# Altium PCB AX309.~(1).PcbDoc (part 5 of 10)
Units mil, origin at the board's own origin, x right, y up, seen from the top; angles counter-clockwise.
Board outline 5185 x 3614 mil, 4 copper layers (Top Layer, GND, Mid-Layer 1, Bottom Layer); 191 components, 352 nets, 1106 pads, 425 vias.
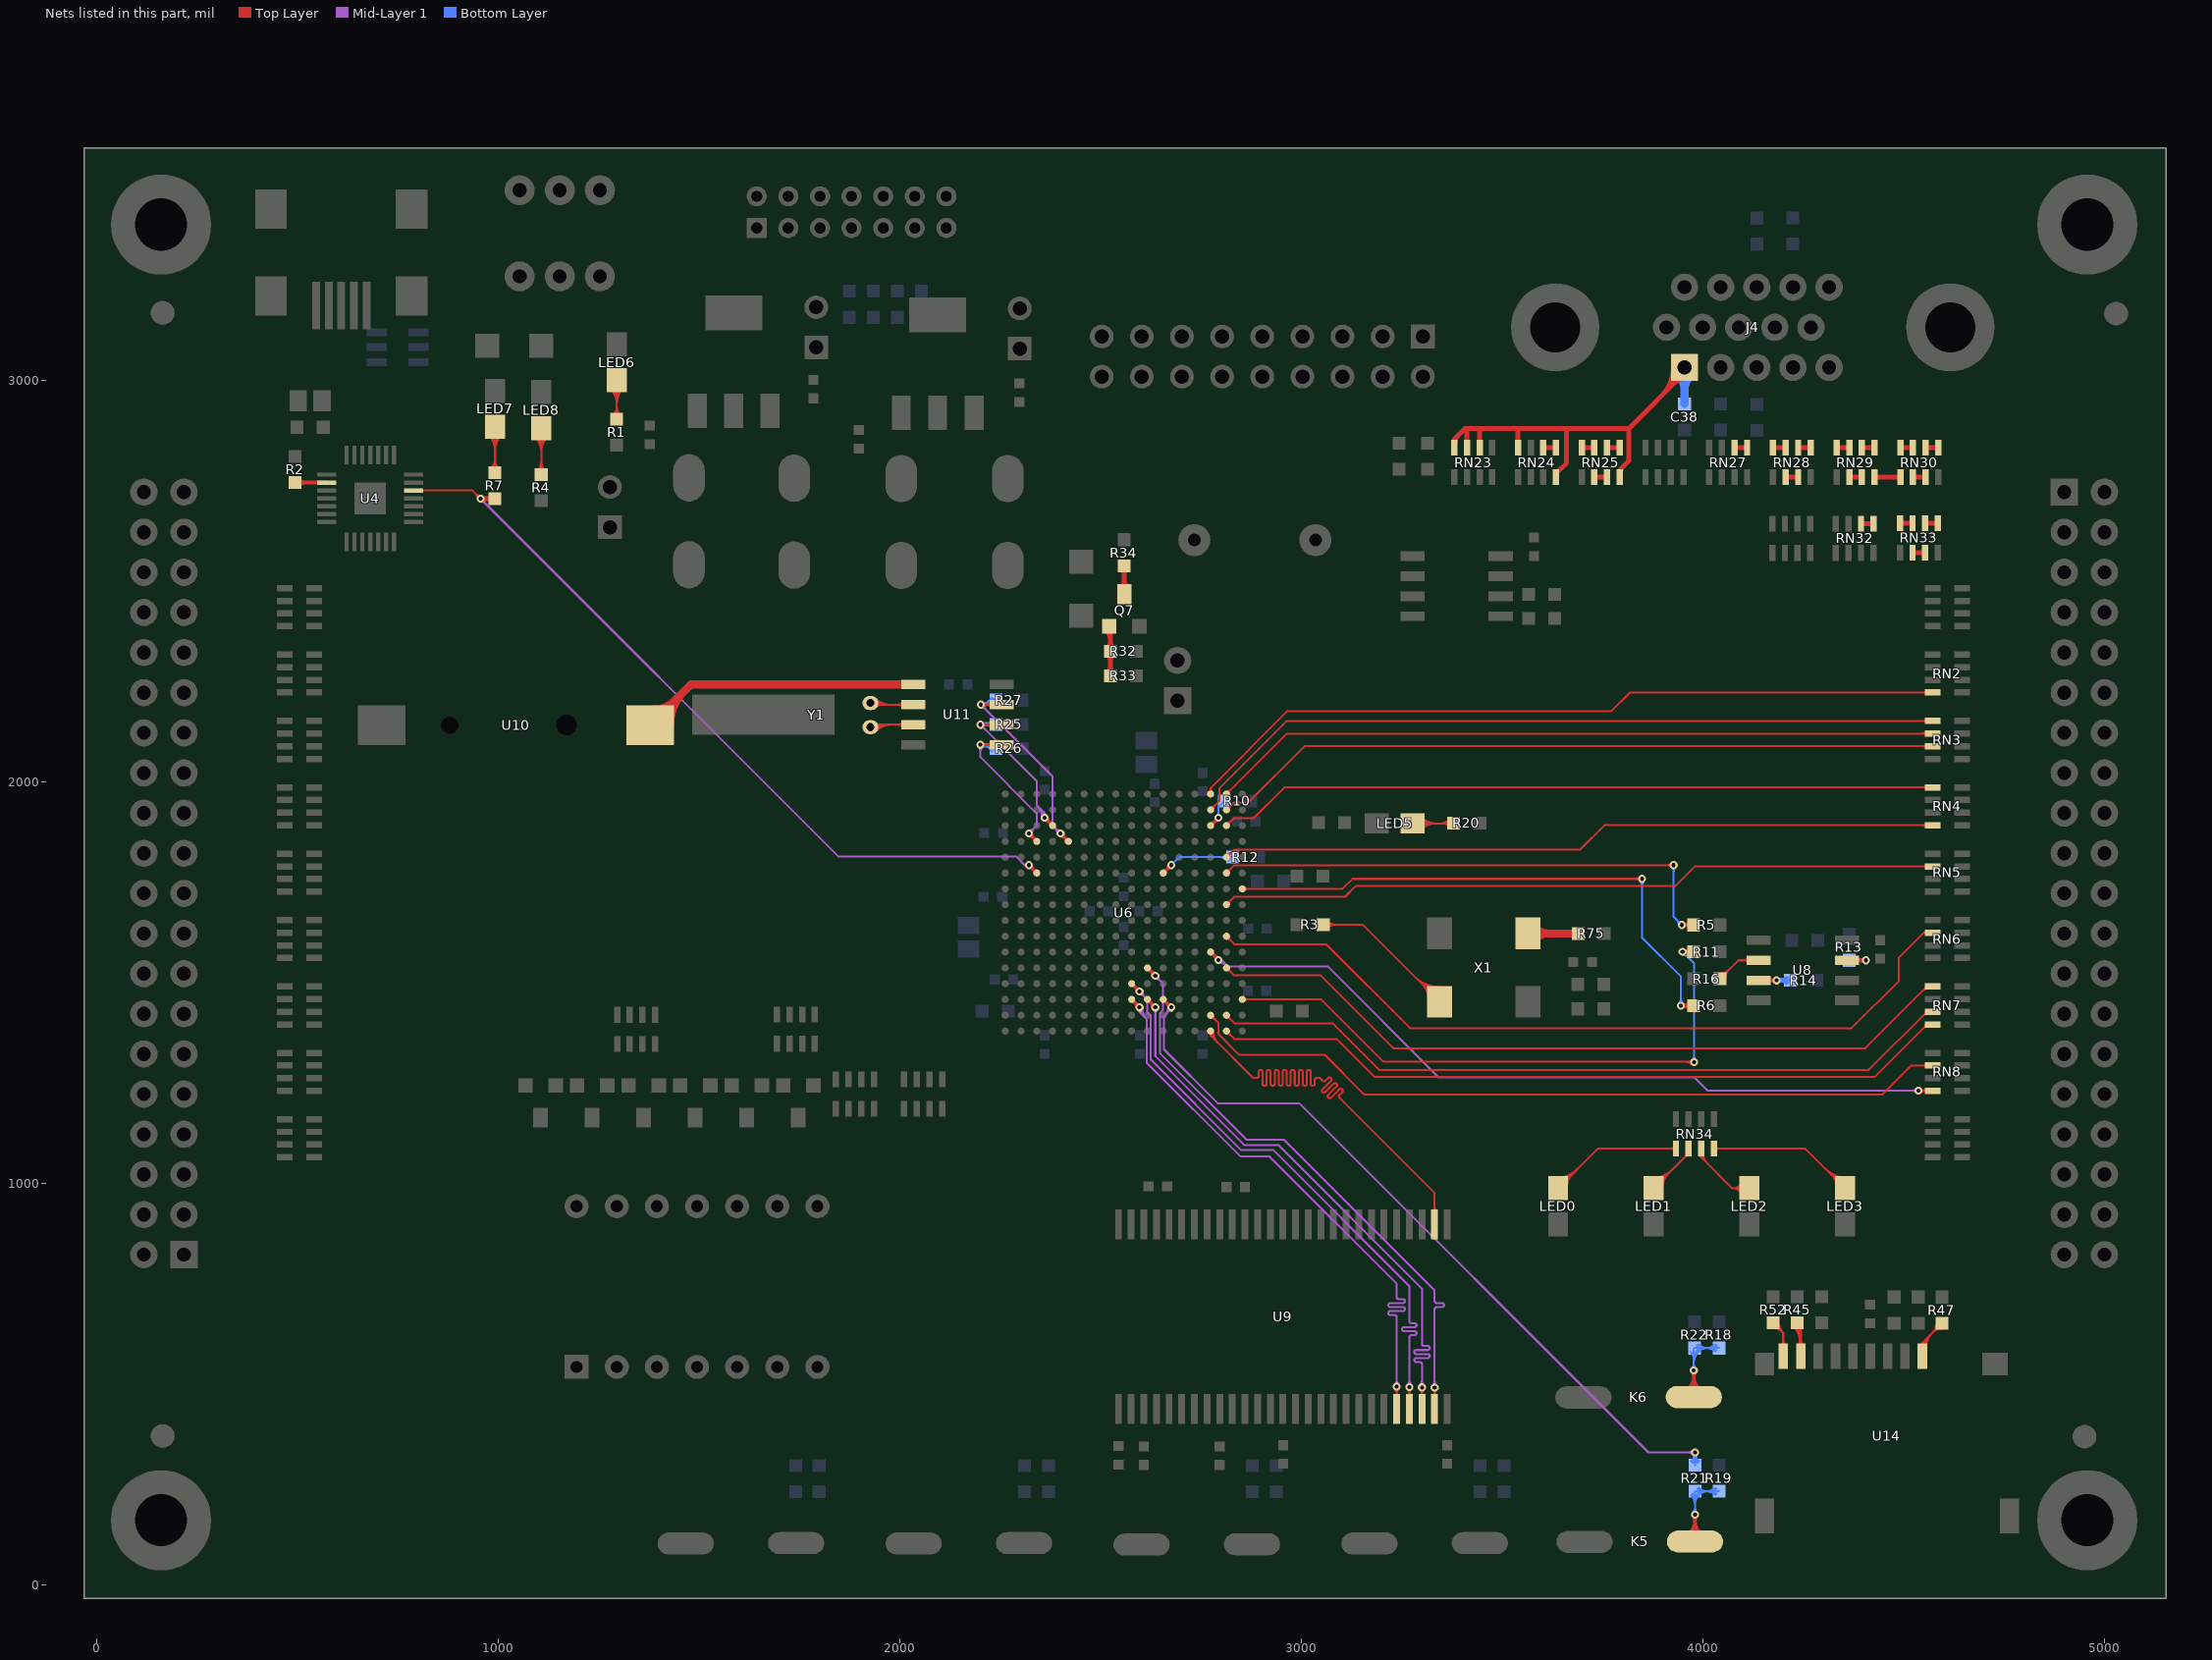
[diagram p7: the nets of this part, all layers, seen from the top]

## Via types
v1: diameter 20, hole 10, Top Layer to Bottom Layer, 328 vias
v2: diameter 30, hole 15, Top Layer to Bottom Layer, 95 vias
v3: diameter 40, hole 20, Top Layer to Bottom Layer, 2 vias

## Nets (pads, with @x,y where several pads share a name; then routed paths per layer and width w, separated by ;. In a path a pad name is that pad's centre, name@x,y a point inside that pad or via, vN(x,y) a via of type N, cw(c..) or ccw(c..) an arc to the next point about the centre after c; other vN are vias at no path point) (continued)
NetK5_1: K5.1 R19.2 R21.2 | length 782.9
  Top Layer w5: K5.1@3963.28,124.72 ccw(c3920.5,167.5) 3981,167.5 ccw(c4041.5,167.5) K5.1@3998.72,124.72 ; K5.1@3966.82,121.18 ccw(c3932.57,155.43) 3981,155.43 ccw(c4029.43,155.43) K5.1@3995.18,121.18 ; K5.1@3970.35,117.65 ccw(c3944.64,143.36) 3981,143.36 ccw(c4017.36,143.36) K5.1@3991.65,117.65 ; v1@3974.95,169.57 cw(c3957.6,156.87) 3978.85,153.58 ; v1@3975.7,168.7 cw(c3962.89,155.89) 3981,155.89 cw(c3999.11,155.89) v1@3986.3,168.7 ; v1@3976.57,167.95 cw(c3967.88,156.08) 3982.42,158.33 ; K5.1@3977,103 K5.1@3981,107 v1(3981,174) ; 3979.58,158.33 cw(c3994.12,156.08) v1@3985.43,167.95 ; 3983.15,153.58 cw(c4004.4,156.87) v1@3987.05,169.57
  Bottom Layer w5: R21.2@3971.45,222.45 cw(c3948.41,199.41) 3981,199.41 cw(c4013.59,199.41) 3990.55,222.45 cw(c4013.59,199.41) 4013.59,232 cw(c4013.59,264.59) R21.2@3990.55,241.55 ; R21.2@3974.99,225.99 cw(c3960.48,211.48) 3981,211.48 cw(c4001.52,211.48) 3987.01,225.99 cw(c4001.52,211.48) 4001.52,232 cw(c4001.52,252.52) R21.2@3987.01,238.01 ; v1@3975.7,179.3 ccw(c3962.89,192.11) 3981,192.11 ccw(c3999.11,192.11) v1@3986.3,179.3 ; v1(3981,174) R21.2@3981,232 R19.2@4041,232 ; R19.2@4031.45,222.45 ccw(c4008.41,199.41) 4008.41,232 ccw(c4008.41,264.59) R19.2@4031.45,241.55 ; R19.2@4034.99,225.99 ccw(c4020.48,211.48) 4020.48,232 ccw(c4020.48,252.52) R19.2@4034.99,238.01
NetK6_2: K6.2 R18.2 R22.2 | length 765.3
  Top Layer w5: K6.2@3960.28,484.72 ccw(c3917.5,527.5) 3978,527.5 ccw(c4038.5,527.5) K6.2@3995.72,484.72 ; K6.2@3963.82,481.18 ccw(c3929.57,515.43) 3978,515.43 ccw(c4026.43,515.43) K6.2@3992.18,481.18 ; K6.2@3967.35,477.65 ccw(c3941.64,503.36) 3978,503.36 ccw(c4014.36,503.36) K6.2@3988.65,477.65 ; v1@3971.91,528.62 cw(c3954.75,516.28) 3975.61,512.87 ; v1@3972.7,527.7 cw(c3959.89,514.89) 3978,514.89 cw(c3996.11,514.89) v1@3983.3,527.7 ; v1@3973.62,526.91 cw(c3964.82,514.67) 3979.7,517.1 ; 3976.3,517.1 cw(c3991.18,514.67) v1@3982.38,526.91 ; K6.2@3978,467 v1(3978,533) ; 3980.39,512.87 cw(c4001.25,516.28) v1@3984.09,528.62
  Bottom Layer w5: R22.2@3970.45,579.45 cw(c3952.24,561.24) 3978,561.24 ; v1@3972.7,538.3 ccw(c3959.89,551.11) 3978,551.11 ccw(c3996.11,551.11) v1@3983.3,538.3 ; v1(3978,533) 3978,587 R22.2@3980,589 R18.2@4041,589 ; 3978,551.58 cw(c4017.42,551.58) 3989.55,579.45 cw(c4012.59,556.41) 4012.59,589 cw(c4012.59,621.59) R22.2@3989.55,598.55 ; 3978,563.65 cw(c4005.35,563.65) 3986.01,582.99 cw(c4000.52,568.48) 4000.52,589 cw(c4000.52,609.52) R22.2@3986.01,595.01 ; R18.2@4031.45,579.45 ccw(c4008.41,556.41) 4008.41,589 ccw(c4008.41,621.59) R18.2@4031.45,598.55 ; R18.2@4034.99,582.99 ccw(c4020.48,568.48) 4020.48,589 ccw(c4020.48,609.52) R18.2@4034.99,595.01
NetLED0_1: LED0.1 RN34.5 | length 578.7
  Top Layer w5: LED0.1@3640,987 3738.85,1085.85 RN34.5@3933.51,1085.85 RN34.5@3933.51,1070.51 ; LED0.1@3640,999.5 ccw(c3640,1029.68) LED0.1@3661.34,1008.34 ; LED0.1@3640,1004.5 ccw(c3640,1046.75) 3669.87,1016.87 ; LED0.1@3640,1009.5 ccw(c3640,1063.82) 3678.41,1025.41 ; LED0.1@3640,1014.5 ccw(c3640,1080.89) 3686.95,1033.95 ; LED0.1@3657.5,992 cw(c3687.68,992) 3666.34,1013.34 ; LED0.1@3662.5,992 cw(c3704.75,992) 3674.87,1021.87 ; RN34.5@3929.71,1082.05 ccw(c3920.54,1072.88) 3920.54,1085.85 ccw(c3920.54,1098.82) RN34.5@3929.71,1089.65
NetLED1_1: LED1.1 RN34.6 | length 363.7
  Top Layer w5: LED1.1@3878.33,987 3965.01,1073.67 RN34.6@3965.01,1085.85 ; LED1.1@3878.33,999.5 ccw(c3878.33,1029.68) LED1.1@3899.67,1008.34 ; LED1.1@3878.33,1004.5 ccw(c3878.33,1046.75) 3908.21,1016.87 ; LED1.1@3878.33,1009.5 ccw(c3878.33,1063.82) 3916.74,1025.41 ; LED1.1@3878.33,1014.5 ccw(c3878.33,1080.89) 3925.28,1033.95 ; LED1.1@3895.83,992 cw(c3926.01,992) 3904.67,1013.34 ; LED1.1@3900.83,992 cw(c3943.08,992) 3913.21,1021.87 ; 3955.58,1064.24 ccw(c3945.78,1074.04) RN34.6@3959.63,1074.04 ; 3956.46,1065.12 cw(c3965.01,1056.57) RN34.6@3965.01,1068.66
NetLED2_1: LED2.1 RN34.7 | length 355.3
  Top Layer w5: RN34.7@3991.88,1074.04 ccw(c4003.75,1074.04) 3995.35,1065.65 ; RN34.7@3993.72,1069.44 cw(c3990.72,1064.5) 3996.5,1064.5 ; RN34.7@3996.5,1085.85 3996.5,1064.5 ; RN34.7@3996.88,1074.04 ccw(c4020.82,1074.04) 4003.89,1057.11 ; RN34.7@3999.29,1069.44 ccw(c4002.29,1064.5) 3996.5,1064.5 ; RN34.7@4001.88,1074.04 ccw(c4037.89,1074.04) 4012.43,1048.57 ; LED2.1@4098.1,974.29 ccw(c4074,957.8) 4074,987 ; LED2.1@4098.1,999.71 cw(c4074,1016.2) 4074,987 ; LED2.1@4102.23,977.12 ccw(c4083.48,964.29) 4083.48,987 ccw(c4083.48,1009.71) LED2.1@4102.23,996.88 ; LED2.1@4129.33,987 LED2.1@4116.67,987 4074,987 ; 3996.5,1064.5 4074,987
NetLED3_1: LED3.1 RN34.8 | length 606.7
  Top Layer w5: RN34.8@4028,1076 RN34.8@4028,1085.85 4256.15,1085.85 LED3.1@4355,987 ; RN34.8@4031.8,1082.05 cw(c4040.97,1072.88) 4040.97,1085.85 cw(c4040.97,1098.82) RN34.8@4031.8,1089.65 ; 4308.05,1033.95 ccw(c4355,1080.89) LED3.1@4355,1014.5 ; 4316.59,1025.41 ccw(c4355,1063.82) LED3.1@4355,1009.5 ; 4320.13,1021.87 cw(c4290.25,992) LED3.1@4332.5,992 ; 4325.13,1016.87 ccw(c4355,1046.75) LED3.1@4355,1004.5 ; 4328.66,1013.34 cw(c4307.32,992) LED3.1@4337.5,992 ; LED3.1@4333.66,1008.34 ccw(c4355,1029.68) LED3.1@4355,999.5
NetLED5_2: LED5.2 R20.2 | length 384.5
  Top Layer w5: LED5.2@3278,1896 R20.2@3380,1896 ; LED5.2@3291.84,1887.16 cw(c3313.18,1865.82) 3313.18,1896 cw(c3313.18,1926.18) LED5.2@3291.84,1904.84 ; LED5.2@3295.37,1883.63 cw(c3325.25,1853.75) 3325.25,1896 cw(c3325.25,1938.25) LED5.2@3295.37,1908.37 ; LED5.2@3298.91,1880.09 cw(c3337.32,1841.68) 3337.32,1896 cw(c3337.32,1950.32) LED5.2@3298.91,1911.91 ; 3344.99,1896 ccw(c3344.99,1932.01) R20.2@3370.45,1906.55 ; 3349.82,1896 cw(c3349.82,1866.82) R20.2@3370.45,1887.45 ; 3357.06,1896 ccw(c3357.06,1919.93) R20.2@3373.99,1903.01 ; 3361.89,1896 cw(c3361.89,1878.89) R20.2@3373.99,1890.99
NetLED6_1: LED6.1 R1.2 | length 379.5
  Top Layer w5: LED6.1@1279.09,2979.09 cw(c1240.68,2940.68) 1295,2940.68 cw(c1349.32,2940.68) LED6.1@1310.91,2979.09 ; LED6.1@1282.63,2982.63 cw(c1252.75,2952.75) 1295,2952.75 cw(c1337.25,2952.75) LED6.1@1307.37,2982.63 ; R1.2@1285.45,2912.55 ccw(c1262.41,2935.59) 1295,2935.59 ccw(c1327.59,2935.59) R1.2@1304.55,2912.55 ; LED6.1@1286.16,2986.16 cw(c1264.82,2964.82) 1295,2964.82 cw(c1325.18,2964.82) LED6.1@1303.84,2986.16 ; R1.2@1288.99,2909.01 ccw(c1274.48,2923.52) 1295,2923.52 ccw(c1315.52,2923.52) R1.2@1301.01,2909.01 ; R1.2@1295,2903 LED6.1@1295,3000
NetLED7_2: LED7.2 R7.2 | length 395.5
  Top Layer w5: LED7.2@976.09,2863.09 cw(c937.68,2824.68) 992,2824.68 cw(c1046.32,2824.68) LED7.2@1007.91,2863.09 ; LED7.2@979.63,2866.63 cw(c949.75,2836.75) 992,2836.75 cw(c1034.25,2836.75) LED7.2@1004.37,2866.63 ; R7.2@981.45,2779.55 ccw(c955.99,2805.01) 992,2805.01 ; LED7.2@983.16,2870.16 cw(c961.82,2848.82) 992,2848.82 cw(c1022.18,2848.82) LED7.2@1000.84,2870.16 ; R7.2@984.99,2776.01 ccw(c968.07,2792.93) 992,2792.93 ; R7.2@992,2771 LED7.2@992,2884 ; 992,2788.11 ccw(c1009.11,2788.11) R7.2@997.01,2776.01 ; 992,2800.18 ccw(c1021.18,2800.18) R7.2@1000.55,2779.55
NetLED8_2: LED8.2 R4.2 | length 398.2
  Top Layer w5: LED8.2@1091.09,2860.09 cw(c1052.68,2821.68) 1107,2821.68 cw(c1161.32,2821.68) LED8.2@1122.91,2860.09 ; LED8.2@1094.63,2863.63 cw(c1064.75,2833.75) 1107,2833.75 cw(c1149.25,2833.75) LED8.2@1119.37,2863.63 ; R4.2@1097.45,2774.85 ccw(c1074.41,2797.89) 1107,2797.89 ccw(c1139.59,2797.89) R4.2@1116.55,2774.85 ; LED8.2@1098.16,2867.16 cw(c1076.82,2845.82) 1107,2845.82 cw(c1137.18,2845.82) LED8.2@1115.84,2867.16 ; R4.2@1100.99,2771.31 ccw(c1086.48,2785.82) 1107,2785.82 ccw(c1127.52,2785.82) R4.2@1113.01,2771.31 ; R4.2@1107,2765.3 LED8.2@1107,2881
NetQ7_1: Q7.1 R32.2 R33.2 | length 279.3
  Top Layer w12: Q7.1@2513.51,2378.51 cw(c2485.79,2350.79) 2525,2350.79 ; R33.2@2517.93,2271.07 ccw(c2500.86,2288.14) 2525,2288.14 ccw(c2549.14,2288.14) R33.2@2532.07,2271.07 ; R32.2@2517.93,2317.93 cw(c2500.86,2300.86) 2525,2300.86 cw(c2549.14,2300.86) R32.2@2532.07,2317.93 ; R32.2@2517.93,2332.07 ccw(c2500.86,2349.14) 2525,2349.14 ccw(c2549.14,2349.14) R32.2@2532.07,2332.07 ; R33.2@2525,2264 R32.2@2525,2325 Q7.1@2525,2384 ; 2525,2365.27 cw(c2543.73,2365.27) Q7.1@2530.49,2378.51
NetQ7_3: Q7.3 R34.1 | length 153.4
  Top Layer w12: Q7.3@2551.51,2482.49 ccw(c2533.44,2500.56) 2559,2500.56 ; R34.1@2551.93,2530.93 cw(c2534.86,2513.86) 2559,2513.86 cw(c2583.14,2513.86) R34.1@2566.07,2530.93 ; Q7.3@2559,2468 R34.1@2559,2538 ; 2559,2505.38 ccw(c2591.38,2505.38) Q7.3@2568.49,2482.49
NetR2_1: R2.1 U4.9 | length 120.3
  Top Layer w10: R2.1@494.1,2745.1 U4.9@572.68,2745.1 ; R2.1@501.78,2737.22 cw(c520.8,2718.2) 520.8,2745.1 ; R2.1@501.78,2752.78 ccw(c520.31,2771.31) 520.31,2745.1
NetR3_2: R3.2 X1.3 | length 799.4
  Top Layer w5: R3.2@3055,1644 3153,1644 X1.3@3345,1452 ; R3.2@3061.01,1637.99 cw(c3075.52,1623.48) 3075.52,1644 cw(c3075.52,1664.52) R3.2@3061.01,1650.01 ; R3.2@3064.55,1634.45 cw(c3087.59,1611.41) 3087.59,1644 cw(c3087.59,1676.59) R3.2@3064.55,1653.55 ; 3282.06,1514.94 ccw(c3345,1577.88) X1.3@3345,1488.87 ; 3290.59,1506.41 ccw(c3345,1560.81) X1.3@3345,1483.87 ; 3299.13,1497.87 ccw(c3345,1543.74) X1.3@3345,1478.87 ; 3301.07,1495.93 cw(c3265.01,1459.87) X1.3@3316,1459.87 ; 3307.67,1489.33 ccw(c3345,1526.67) X1.3@3345,1473.87 ; 3309.6,1487.4 cw(c3282.08,1459.87) X1.3@3321,1459.87 ; X1.3@3316.2,1480.8 ccw(c3345,1509.6) X1.3@3345,1468.87 ; X1.3@3318.14,1478.86 cw(c3299.15,1459.87) X1.3@3326,1459.87
NetR5_1: R5.1 U6.R11 | length 1556.1
  Top Layer w5: U6.R11@2813.91,1772.43 2833.59,1792.11 v1(3927.89,1792.11) ; U6.R11@2813.91,1778.78 ccw(c2813.91,1794.13) 2824.76,1783.28 ccw(c2835.61,1772.43) U6.R11@2820.26,1772.43 ; v1@3922.59,1786.81 ccw(c3909.78,1774) 3909.78,1792.11 ccw(c3909.78,1810.22) v1@3922.59,1797.41 ; v1@3953.04,1637.44 cw(c3958.99,1630.87) 3961.29,1639.44 cw(c3963.59,1648.01) v1@3955.14,1645.29 ; v1@3953.04,1648.56 ccw(c3958.99,1655.13) 3961.29,1646.56 ccw(c3963.59,1637.99) v1@3955.14,1640.71 ; v1@3953.3,1637.7 cw(c3966.11,1624.89) 3966.11,1643 cw(c3966.11,1661.11) v1@3953.3,1648.3 ; R5.1@3967.9,1634.05 ccw(c3948,1616.42) v1(3948,1643) ; R5.1@3967.9,1651.95 cw(c3948,1669.58) v1(3948,1643) ; R5.1@3971.64,1637.36 ccw(c3959.11,1626.26) 3959.11,1643 ccw(c3959.11,1659.74) R5.1@3971.64,1648.64 ; R5.1@3978,1643 v1(3948,1643)
  Bottom Layer w5: v1@3922.59,1786.81 cw(c3909.78,1774) 3927.89,1774 cw(c3946,1774) v1@3933.19,1786.81 ; v1(3927.89,1792.11) 3927.89,1663.11 v1(3948,1643) ; v1@3940.5,1643 ccw(c3922.39,1643) 3935.2,1655.8 ccw(c3948,1668.61) v1@3948,1650.5
NetR6_1: R6.1 U6.T10 | length 1660.6
  Top Layer w5: U6.T10@2853.28,1733.06 3103.06,1733.06 3128,1758 v1(3849,1758) ; U6.T10@2857.77,1728.56 cw(c2868.63,1717.7) 2868.63,1733.06 cw(c2868.63,1748.41) U6.T10@2857.77,1737.55 ; v1@3843.7,1752.7 ccw(c3830.89,1739.89) 3830.89,1758 ccw(c3830.89,1776.11) v1@3843.7,1763.3 ; v1@3950.29,1435.85 cw(c3958.06,1424.68) 3961.59,1437.82 cw(c3965.11,1450.97) v1@3952.79,1445.19 ; v1@3950.29,1448.15 ccw(c3958.06,1459.32) 3961.59,1446.18 ccw(c3965.11,1433.03) v1@3952.79,1438.81 ; v1@3951.3,1436.7 cw(c3964.11,1423.89) 3964.11,1442 cw(c3964.11,1460.11) v1@3951.3,1447.3 ; R6.1@3968.33,1432.58 ccw(c3946,1410.83) v1(3946,1442) ; R6.1@3968.33,1451.42 cw(c3946,1473.17) v1(3946,1442) ; R6.1@3971.91,1436.07 ccw(c3957.85,1422.37) 3957.85,1442 ccw(c3957.85,1461.63) R6.1@3971.91,1447.93 ; R6.1@3978,1442 v1(3946,1442)
  Bottom Layer w5: v1@3843.7,1752.7 cw(c3830.89,1739.89) 3849,1739.89 cw(c3867.11,1739.89) v1@3854.3,1752.7 ; v1(3849,1758) 3849,1611.75 3946,1514.75 v1(3946,1442) ; v1@3940.7,1447.3 ccw(c3927.89,1460.11) 3946,1460.11 ccw(c3964.11,1460.11) v1@3951.3,1447.3
NetR10_2: R10.2 U6.P14 | length 227.8
  Top Layer w5: U6.P14@2774.54,1890.54 v1(2794.22,1910.22) ; U6.P14@2774.54,1896.89 ccw(c2774.54,1912.24) 2785.39,1901.39 ccw(c2796.24,1890.54) U6.P14@2780.89,1890.54 ; U6.P14@2776.89,1896.48 ccw(c2766.81,1913.94) v1@2786.79,1911.23 ; U6.P14@2780.48,1892.89 cw(c2797.94,1882.81) v1@2795.23,1902.79 ; 2783.77,1900.46 ccw(c2780.32,1906.44) v1@2786.98,1908.25 ; 2784.46,1899.77 cw(c2790.44,1896.32) v1@2792.25,1902.98 ; 2785.58,1901.72 cw(c2796.21,1895.58) v1@2794.56,1907.74 ; 2785.72,1901.58 ccw(c2779.58,1912.21) v1@2791.74,1910.56 ; v1@2786.72,1910.22 cw(c2768.61,1910.22) 2781.42,1897.42 cw(c2794.22,1884.61) v1@2794.22,1902.72 ; 2786.27,1902.92 ccw(c2780.15,1906.45) 2786.98,1908.28 cw(c2780.15,1906.45) 2786.27,1902.92 ; 2786.92,1902.27 cw(c2790.45,1896.15) 2792.28,1902.98 ccw(c2790.45,1896.15) 2786.92,1902.27
  Bottom Layer w5: v1(2794.22,1910.22) 2794.22,1937.22 R10.2@2809,1952
NetR11_1: R11.1 U6.T3 | length 1731.9
  Top Layer w5: U6.T3@2853.28,1457.46 3049.54,1457.46 3205,1302 v1@3979,1302 ; U6.T3@2857.77,1452.97 cw(c2868.63,1442.11) 2868.63,1457.46 cw(c2868.63,1472.81) U6.T3@2857.77,1461.96 ; v1@3955.3,1570.7 cw(c3968.11,1557.89) 3968.11,1576 cw(c3968.11,1594.11) v1@3955.3,1581.3 ; v1@3955.83,1571.29 cw(c3959.82,1568.07) 3961.14,1573.01 cw(c3962.47,1577.96) v1@3957.41,1577.17 ; v1@3955.83,1580.71 ccw(c3959.82,1583.93) 3961.14,1578.99 ccw(c3962.47,1574.04) v1@3957.41,1574.83 ; 3958.48,1302 cw(c3958.48,1280.48) v1@3973.7,1295.7 ; 3963.31,1302 ccw(c3963.31,1316.69) v1@3973.7,1306.3 ; R11.1@3967.44,1567.59 ccw(c3950,1553.72) v1(3950,1576) ; R11.1@3967.44,1584.41 cw(c3950,1598.28) v1(3950,1576) ; R11.1@3971.35,1570.71 ccw(c3960.37,1561.97) 3960.37,1576 ccw(c3960.37,1590.03) R11.1@3971.35,1581.29 ; R11.1@3978,1576 v1(3950,1576)
  Bottom Layer w5: v1@3950,1568.5 cw(c3950,1550.39) 3962.8,1563.2 cw(c3975.61,1576) v1@3957.5,1576 ; v1(3950,1576) 3979,1547 v1(3979,1301) ; v1@3973.7,1306.3 ccw(c3960.89,1319.11) 3979,1319.11 ccw(c3997.11,1319.11) v1@3984.3,1306.3
NetR12_2: R12.2 U6.L11 | length 424.5
  Top Layer w5: U6.L11@2656.43,1772.43 v1(2676.11,1792.11) ; U6.L11@2656.43,1778.78 ccw(c2656.43,1794.13) 2667.28,1783.28 ccw(c2678.13,1772.43) U6.L11@2662.78,1772.43 ; U6.L11@2658.78,1778.37 ccw(c2648.7,1795.83) v1@2668.68,1793.12 ; U6.L11@2662.37,1774.78 cw(c2679.83,1764.7) v1@2677.12,1784.68 ; 2665.66,1782.35 ccw(c2662.21,1788.33) v1@2668.87,1790.14 ; 2666.35,1781.66 cw(c2672.33,1778.21) v1@2674.14,1784.87 ; 2667.47,1783.61 cw(c2678.1,1777.47) v1@2676.45,1789.63 ; 2667.61,1783.47 ccw(c2661.47,1794.1) v1@2673.63,1792.45 ; v1@2668.61,1792.11 cw(c2650.5,1792.11) 2663.31,1779.31 cw(c2676.11,1766.5) v1@2676.11,1784.61 ; v1@2668.87,1790.17 cw(c2662.04,1788.34) 2668.16,1784.81 ccw(c2662.04,1788.34) v1@2668.87,1790.17 ; 2668.81,1784.16 cw(c2672.34,1778.04) 2674.17,1784.87 ccw(c2672.34,1778.04) 2668.81,1784.16
  Bottom Layer w5: v1(2676.11,1792.11) 2696,1812 R12.2@2829,1812 ; R12.2@2819.45,1802.45 ccw(c2796.41,1779.41) 2796.41,1812 ccw(c2796.41,1844.59) R12.2@2819.45,1821.55 ; R12.2@2822.99,1805.99 ccw(c2808.48,1791.48) 2808.48,1812 ccw(c2808.48,1832.52) R12.2@2822.99,1818.01
NetR13_1: R13.1 U8.7 | length 374.1
  Top Layer w5: U8.7@4360,1555 v1(4407,1555) ; U8.7@4384.72,1548.28 cw(c4400.94,1532.07) 4400.94,1555 cw(c4400.94,1577.93) U8.7@4384.72,1561.72 ; 4392.09,1552.63 cw(c4394.54,1543.5) v1@4401.49,1549.91 ; 4392.09,1557.37 ccw(c4394.54,1566.5) v1@4401.49,1560.09 ; 4392.76,1552.81 ccw(c4389.47,1565.12) v1@4400.5,1558.75 ; 4392.76,1557.19 cw(c4389.47,1544.88) v1@4400.5,1551.25 ; v1@4401.7,1549.7 ccw(c4388.89,1536.89) 4388.89,1555 ccw(c4388.89,1573.11) v1@4401.7,1560.3
  Bottom Layer w5: R13.1@4365,1555 v1(4407,1555) ; R13.1@4371.01,1548.99 cw(c4385.52,1534.48) 4385.52,1555 cw(c4385.52,1575.52) R13.1@4371.01,1561.01 ; R13.1@4374.55,1545.45 cw(c4397.59,1522.41) 4397.59,1555 cw(c4397.59,1587.59) R13.1@4374.55,1564.55 ; 4386.62,1552.3 cw(c4391.11,1534.05) v1@4402.47,1549.02 ; 4386.62,1557.7 ccw(c4391.11,1575.95) v1@4402.47,1560.98 ; 4394.16,1554.15 ccw(c4391.66,1564.27) v1@4400.58,1558.88 ; 4394.16,1555.85 cw(c4391.66,1545.73) v1@4400.58,1551.12 ; 4396.79,1554.8 cw(c4399.26,1544.79) v1@4405.49,1553.01 ; 4396.79,1555.2 ccw(c4399.26,1565.21) v1@4405.49,1556.99 ; v1@4401.7,1549.7 ccw(c4388.89,1536.89) 4388.89,1555 ccw(c4388.89,1573.11) v1@4401.7,1560.3
NetR14_1: R14.1 U8.3 | length 342.7
  Top Layer w5: U8.3@4140,1505 v1(4184,1505) ; U8.3@4164.72,1498.28 cw(c4180.94,1482.07) 4180.94,1505 cw(c4180.94,1527.93) U8.3@4164.72,1511.72 ; v1@4177.05,1502.19 ccw(c4168.37,1498.68) 4170.8,1507.72 ccw(c4172.75,1515.03) v1@4178.4,1509.99 ; v1@4177.05,1507.81 cw(c4168.37,1511.32) 4170.8,1502.28 cw(c4172.75,1494.97) v1@4178.4,1500.01 ; v1@4178.7,1499.7 ccw(c4165.89,1486.89) 4165.89,1505 ccw(c4165.89,1523.11) v1@4178.7,1510.3
  Bottom Layer w5: v1(4184,1505) R14.1@4219,1505 ; v1@4188.12,1498.73 cw(c4197.32,1484.72) 4201.66,1500.91 ; v1@4188.12,1511.27 ccw(c4197.32,1525.28) 4201.66,1509.09 ; v1@4189.3,1499.7 cw(c4202.11,1486.89) 4202.11,1505 cw(c4202.11,1523.11) v1@4189.3,1510.3 ; v1@4190.5,1501.25 cw(c4204.33,1493.26) 4200.2,1508.69 ; v1@4190.5,1508.75 ccw(c4204.33,1516.74) 4200.2,1501.31 ; R14.1@4209.45,1495.45 ccw(c4186.41,1472.41) 4186.41,1505 ccw(c4186.41,1537.59) R14.1@4209.45,1514.55 ; R14.1@4212.99,1498.99 ccw(c4198.48,1484.48) 4198.48,1505 ccw(c4198.48,1525.52) R14.1@4212.99,1511.01
NetR16_2: R16.2 U8.2 | length 235.5
  Top Layer w5: R16.2@4043,1509 4089,1555 U8.2@4140,1555 ; R16.2@4043,1517.5 ccw(c4043,1538.02) 4057.51,1523.51 ccw(c4072.02,1509) R16.2@4051.5,1509 ; R16.2@4043,1522.5 ccw(c4043,1555.09) 4066.05,1532.05 ccw(c4089.09,1509) R16.2@4056.5,1509 ; U8.2@4115.28,1548.28 ccw(c4099.06,1532.07) 4099.06,1555 ccw(c4099.06,1577.93) U8.2@4115.28,1561.72
NetR45_2: R45.2 U14.8 | length 259.4
  Top Layer w6: R45.2@4226.81,642.81 cw(c4184.26,600.26) U14.8@4244.43,600.26 ; R45.2@4231.05,647.05 cw(c4198.74,614.74) 4244.43,614.74 ; R45.2@4235.29,651.29 cw(c4213.23,629.23) 4244.43,629.23 ; R45.2@4236,652 4244.43,643.57 U14.8@4244.43,568.82 ; U14.8@4237.58,594.04 ccw(c4219.13,608.94) 4242.58,612.5 ; U14.8@4238.2,594.73 ccw(c4223.16,609.78) 4244.43,609.78 ccw(c4265.7,609.78) U14.8@4250.66,594.73 ; 4243.62,605.59 ccw(c4258.7,607.88) U14.8@4249.66,595.6
NetR47_2: R47.2 U14.1 | length 320.2
  Top Layer w5: U14.1@4541.89,588.5 cw(c4562.15,588.5) 4547.83,602.83 ; U14.1@4543.94,597.07 ccw(c4541.59,602.58) 4547.58,602.58 ; U14.1@4546.89,588.5 cw(c4579.22,588.5) 4556.36,611.36 ; U14.1@4547.58,568.82 4547.58,602.58 ; U14.1@4551.23,597.07 cw(c4553.57,602.58) 4547.58,602.58 ; U14.1@4551.89,588.5 cw(c4596.29,588.5) 4564.9,619.9 ; U14.1@4556.89,588.5 cw(c4613.36,588.5) 4573.43,628.43 ; R47.2@4582.5,651 cw(c4549.91,651) 4572.95,627.95 cw(c4596,604.91) R47.2@4596,637.5 ; R47.2@4587.5,651 cw(c4566.98,651) 4581.49,636.49 cw(c4596,621.98) R47.2@4596,642.5 ; R47.2@4596,651 4547.58,602.58
NetR52_2: R52.2 U14.9 | length 202.8
  Top Layer w6: R52.2@4176,639 cw(c4176,607.62) 4198.19,629.81 cw(c4220.38,652) R52.2@4189,652 ; R52.2@4176,645 cw(c4176,628.1) 4187.95,640.05 cw(c4199.9,652) R52.2@4183,652 ; R52.2@4176,652 4201.13,626.87 U14.9@4201.13,568.82 ; U14.9@4194.9,594.73 ccw(c4179.85,609.78) 4201.13,609.78 ccw(c4222.4,609.78) U14.9@4207.36,594.73
NetR75_1: R75.1 X1.1 | length 191.5
  Top Layer w20: X1.1@3565,1622 R75.1@3675,1622 ; X1.1@3580.2,1606.8 cw(c3616.9,1570.1) 3616.9,1622 cw(c3616.9,1673.9) X1.1@3580.2,1637.2
NetRN24_1: RN24.1 RN24.2 | length 31.5
  Top Layer w12: RN24.2@3603.22,2832 RN24.1@3634.71,2832
NetRN25_1: RN25.1 RN25.2 | length 31.5
  Top Layer w12: RN25.2@3761.93,2832 RN25.1@3793.43,2832
NetRN25_3: RN25.3 RN25.4 | length 31.5
  Top Layer w12: RN25.4@3698.94,2832 RN25.3@3730.44,2832
NetRN25_6: RN25.6 RN25.7 | length 31.5
  Top Layer w12: RN25.6@3730.44,2758.85 RN25.7@3761.93,2758.85
NetRN27_1: RN27.1 RN27.2 | length 31.5
  Top Layer w12: RN27.2@4079.36,2832 RN27.1@4110.86,2832
NetRN28_1: RN28.1 RN28.2 | length 31.5
  Top Layer w12: RN28.2@4239.5,2832 RN28.1@4271,2832
NetRN28_3: RN28.3 RN28.4 | length 31.5
  Top Layer w12: RN28.4@4176.51,2832 RN28.3@4208.01,2832
NetRN28_6: RN28.6 RN28.7 | length 31.5
  Top Layer w12: RN28.6@4208.01,2758.85 RN28.7@4239.5,2758.85
NetRN29_1: RN29.1 RN29.2 | length 31.5
  Top Layer w12: RN29.2@4396.5,2832 RN29.1@4428,2832
NetRN29_3: RN29.3 RN29.4 | length 31.5
  Top Layer w12: RN29.4@4333.51,2832 RN29.3@4365.01,2832
NetRN29_6: RN29.6 RN29.7 | length 31.5
  Top Layer w12: RN29.6@4365.01,2758.85 RN29.7@4396.5,2758.85
NetRN29_8: RN29.8 RN30.5 | length 64.5
  Top Layer w12: RN29.8@4428,2758.85 RN30.5@4492.51,2758.85
NetRN30_1: RN30.1 RN30.2 | length 31.5
  Top Layer w12: RN30.2@4555.5,2832 RN30.1@4587,2832
NetRN30_3: RN30.3 RN30.4 | length 31.5
  Top Layer w12: RN30.4@4492.51,2832 RN30.3@4524.01,2832
NetRN30_6: RN30.6 RN30.7 | length 31.5
  Top Layer w12: RN30.6@4524.01,2758.85 RN30.7@4555.5,2758.85
NetRN32_1: RN32.1 RN32.2 | length 31.5
  Top Layer w12: RN32.2@4394.5,2643 RN32.1@4426,2643
NetRN33_1: RN33.1 RN33.2 | length 31.5
  Top Layer w12: RN33.2@4554.5,2644 RN33.1@4586,2644
NetRN33_3: RN33.3 RN33.4 | length 31.5
  Top Layer w12: RN33.4@4491.51,2644 RN33.3@4523.01,2644
NetRN33_6: RN33.6 RN33.7 | length 31.5
  Top Layer w12: RN33.6@4523.01,2570.85 RN33.7@4554.5,2570.85
NetU10_1: U10.1 U11.1 | length 901
  Top Layer w20: U10.1@1378.63,2141 1479.63,2242 U11.1@2034,2242 ; U10.1@1388.47,2180.21 ccw(c1388.47,2251.12) 1438.61,2200.98 ; U10.1@1407.68,2141 cw(c1477.83,2141) 1428.23,2190.6 ; U10.1@1427.68,2141 cw(c1546.11,2141) 1462.37,2224.74
NetU11_2: U11.2 Y1.1 | length 245.8
  Top Layer w5: Y1.1@1931,2192 U11.2@2034,2192 ; Y1.1@1933.04,2199.54 ccw(c1951.23,2217.73) 1951.23,2192 ; Y1.1@1936.57,2203.07 ccw(c1963.3,2229.8) 1963.3,2192 ; Y1.1@1940.11,2185.39 cw(c1956.06,2169.44) 1956.06,2192 ; Y1.1@1940.11,2206.61 ccw(c1975.37,2241.87) 1975.37,2192 ; U11.2@2009.28,2185.28 ccw(c1993.07,2169.07) 1993.07,2192 ccw(c1993.07,2214.93) U11.2@2009.28,2198.72
NetU11_3: U11.3 Y1.2 | length 254.5
  Top Layer w5: Y1.2@1933,2142 U11.3@2034,2142 ; Y1.2@1933.04,2132.46 cw(c1956.06,2109.44) 1956.06,2142 ; Y1.2@1936.57,2128.93 cw(c1968.13,2097.37) 1968.13,2142 ; Y1.2@1940.11,2125.39 cw(c1980.2,2085.3) 1980.2,2142 ; Y1.2@1940.11,2146.61 ccw(c1951.23,2157.73) 1951.23,2142 ; U11.3@2009.28,2135.28 ccw(c1993.07,2119.07) 1993.07,2142 ccw(c1993.07,2164.93) U11.3@2009.28,2148.72
P2: RN8.2 U6.P2 | length 1971.4
  Top Layer w5: U6.P2@2774.54,1411.74 cw(c2774.54,1396.39) 2785.39,1407.24 cw(c2796.24,1418.09) U6.P2@2780.89,1418.09 ; U6.P2@2774.54,1418.09 2794,1398.63 2794,1371 2845,1320 3058,1320 3158,1220 4447,1220 4519.88,1292.88 RN8.2@4573,1292.88 ; RN8.2@4557.39,1289.08 ccw(c4548.22,1279.9) 4548.22,1292.88 ccw(c4548.22,1305.85) RN8.2@4557.39,1296.68
P6: RN8.4 U6.P6 | length 2225.6
  Top Layer w5: U6.P6@2774.54,1569.22 cw(c2774.54,1553.87) 2785.39,1564.72 cw(c2796.24,1575.57) U6.P6@2780.89,1575.57 ; U6.P6@2774.54,1575.57 v1(2794.22,1555.89) ; U6.P6@2776.89,1569.63 cw(c2766.81,1552.17) v1@2786.79,1554.88 ; U6.P6@2780.48,1573.22 ccw(c2797.94,1583.3) v1@2795.23,1563.32 ; 2783.77,1565.65 cw(c2780.32,1559.67) v1@2786.98,1557.86 ; 2784.46,1566.34 ccw(c2790.44,1569.79) v1@2792.25,1563.13 ; 2785.58,1564.39 ccw(c2796.21,1570.53) v1@2794.56,1558.37 ; 2785.72,1564.53 cw(c2779.58,1553.9) v1@2791.74,1555.55 ; v1@2786.72,1555.89 ccw(c2768.61,1555.89) 2781.42,1568.69 ccw(c2794.22,1581.5) v1@2794.22,1563.39 ; v1(4538,1230) RN8.4@4572.89,1230 ; v1@4543.3,1224.7 cw(c4556.11,1211.89) 4556.11,1230 cw(c4556.11,1248.11) v1@4543.3,1235.3 ; v1@4544.5,1233.75 ccw(c4552.57,1238.41) 4550.16,1229.41 ; v1@4544.78,1226.8 cw(c4549.09,1224.77) 4550.32,1229.36 ; v1@4547.94,1230 cw(c4547.94,1216.64) RN8.4@4557.39,1226.09 ; 4548.49,1230 ccw(c4548.49,1242.59) RN8.4@4557.39,1233.69 ; v1@2786.98,1557.83 ccw(c2780.15,1559.66) 2786.27,1563.19 cw(c2780.15,1559.66) v1@2786.98,1557.83 ; 2786.92,1563.84 ccw(c2790.45,1569.96) 2792.28,1563.13 cw(c2790.45,1569.96) 2786.92,1563.84
  Mid-Layer 1 w5: v1(2794.22,1555.89) 2801.11,1555.89 2817,1540 ; v1@2794.38,1553.39 cw(c2795.62,1534.25) 2809.19,1547.81 ; v1@2794.7,1548.4 cw(c2796.57,1519.57) 2817,1540 ; v1@4532.7,1224.7 ccw(c4519.89,1211.89) 4519.89,1230 ccw(c4519.89,1248.11) v1@4532.7,1235.3 ; v1(4538,1230) 4013,1230 3980,1263 3343,1263 3066,1540 2817,1540
P15: RN3.1 U6.P15 | length 1953.2
  Top Layer w5: U6.P15@2774.54,1929.91 2796,1951.37 2796,1983 2964.25,2151.25 RN3.1@4573,2151.25 ; U6.P15@2774.54,1936.26 ccw(c2774.54,1951.61) 2785.39,1940.76 ccw(c2796.24,1929.91) U6.P15@2780.89,1929.91 ; RN3.1@4557.39,2147.45 ccw(c4548.22,2138.28) 4548.22,2151.25 ccw(c4548.22,2164.22) RN3.1@4557.39,2155.05
P16: RN2.4 U6.P16 | length 1956.4
  Top Layer w5: U6.P16@2770.06,1973.79 ccw(c2759.4,1984.53) 2774.54,1984.53 ; U6.P16@2774.54,1969.28 2774.54,1984.54 ; U6.P16@2779.01,1973.79 cw(c2789.67,1984.53) 2774.54,1984.53 ; RN2.4@4557.39,2218.34 ccw(c4548.22,2209.16) 4548.22,2222.14 ccw(c4548.22,2235.11) RN2.4@4557.39,2225.94 ; RN2.4@4573,2222.14 3819.14,2222.14 3773,2176 2966,2176 2774.54,1984.54
R1: RN7.3 U6.R2 | length 1919.9
  Top Layer w5: U6.R2@2813.91,1411.74 cw(c2813.91,1396.39) 2824.76,1407.24 cw(c2835.61,1418.09) U6.R2@2820.26,1418.09 ; U6.R2@2813.91,1418.09 2834,1398 3078,1398 3194,1282 4414,1282 4558.76,1426.76 RN7.3@4573,1426.76 ; 4547.86,1415.86 cw(c4561.19,1402.54) RN7.3@4561.19,1421.38 ; RN7.3@4553.73,1421.73 ccw(c4548.71,1426.76) RN7.3@4555.82,1426.76
R2: RN7.4 U6.R1 | length 1905.5
  Top Layer w5: U6.R1@2813.91,1372.37 cw(c2813.91,1357.02) 2824.76,1367.87 cw(c2835.61,1378.72) U6.R1@2820.26,1378.72 ; U6.R1@2813.91,1378.72 2833.63,1359 3088,1359 3183,1264 4428,1264 4559.26,1395.26 RN7.4@4573,1395.26 ; 4548.72,1384.72 cw(c4561.19,1372.26) RN7.4@4561.19,1389.89 ; RN7.4@4553.38,1389.38 ccw(c4547.49,1395.26) RN7.4@4555.82,1395.26
R5: RN7.1 U6.R5 | length 1950.2
  Top Layer w5: U6.R5@2813.91,1529.85 cw(c2813.91,1514.5) 2824.76,1525.35 cw(c2835.61,1536.2) U6.R5@2820.26,1536.2 ; U6.R5@2813.91,1536.2 2832.11,1518 3048,1518 3230,1336 4405,1336 4558.75,1489.75 RN7.1@4573,1489.75 ; 4547.85,1478.85 cw(c4561.19,1465.51) RN7.1@4561.19,1484.38 ; RN7.1@4553.74,1484.74 ccw(c4548.73,1489.75) RN7.1@4555.81,1489.75
R7: RN6.2 U6.R7 | length 2024.9
  Top Layer w5: U6.R7@2813.91,1608.59 cw(c2813.91,1593.24) 2824.76,1604.09 cw(c2835.61,1614.94) U6.R7@2820.26,1614.94 ; U6.R7@2813.91,1614.94 2833.59,1595.26 3061.74,1595.26 3271,1386 4371,1386 4489,1504 4489,1562 4550.63,1623.63 ; RN6.2@4556.84,1620.47 ccw(c4550.63,1615.94) 4550.63,1623.63 ; RN6.2@4556.84,1626.79 cw(c4550.63,1631.32) 4550.63,1623.63 ; RN6.2@4573,1623.63 4550.63,1623.63
R9: RN5.2 U6.R9 | length 1843.1
  Top Layer w5: U6.R9@2813.91,1693.68 2833.59,1713.37 3109.37,1713.37 3136,1740 3932,1740 3981,1789 RN5.2@4573,1789 ; U6.R9@2813.91,1700.04 ccw(c2813.91,1715.39) 2824.76,1704.54 ccw(c2835.61,1693.68) U6.R9@2820.26,1693.68 ; RN5.2@4557.39,1785.2 ccw(c4548.22,1776.03) 4548.22,1789 ccw(c4548.22,1801.98) RN5.2@4557.39,1792.8
R12: RN4.4 U6.R12 | length 1836.6
  Top Layer w5: U6.R12@2813.91,1811.8 2833.11,1831 3695,1831 3755.39,1891.39 RN4.4@4573,1891.39 ; U6.R12@2813.91,1818.15 ccw(c2813.91,1833.5) 2824.76,1822.65 ccw(c2835.61,1811.8) U6.R12@2820.26,1811.8 ; RN4.4@4557.39,1887.59 ccw(c4548.22,1878.41) 4548.22,1891.39 ccw(c4548.22,1904.36) RN4.4@4557.39,1895.19
R14: RN4.1 U6.R14 | length 1843.1
  Top Layer w5: U6.R14@2813.91,1890.54 2832.37,1909 2881,1909 2957.88,1985.88 RN4.1@4573,1985.88 ; U6.R14@2813.91,1896.89 ccw(c2813.91,1912.24) 2824.76,1901.39 ccw(c2835.61,1890.54) U6.R14@2820.26,1890.54 ; RN4.1@4557.39,1982.08 ccw(c4548.22,1972.9) 4548.22,1985.88 ccw(c4548.22,1998.85) RN4.1@4557.39,1989.67
R15: RN3.3 U6.R15 | length 1869.2
  Top Layer w5: U6.R15@2813.91,1929.91 2832,1948 2868,1948 3008.26,2088.26 RN3.3@4573,2088.26 ; U6.R15@2813.91,1936.26 ccw(c2813.91,1951.61) 2824.76,1940.76 ccw(c2835.61,1929.91) U6.R15@2820.26,1929.91 ; RN3.3@4557.39,2084.46 ccw(c4548.22,2075.28) 4548.22,2088.26 ccw(c4548.22,2101.23) RN3.3@4557.39,2092.06
R16: RN3.2 U6.R16 | length 1865.9
  Top Layer w5: U6.R16@2813.91,1969.28 2964.38,2119.75 RN3.2@4573,2119.75 ; U6.R16@2813.91,1975.63 ccw(c2813.91,1990.98) 2824.76,1980.13 ccw(c2835.61,1969.28) U6.R16@2820.26,1969.28 ; RN3.2@4557.39,2115.95 ccw(c4548.22,2106.78) 4548.22,2119.75 ccw(c4548.22,2132.73) RN3.2@4557.39,2123.55
RED: C38.1 J4.1 RN23.2 RN23.3 RN23.4 RN24.4 RN24.8 RN25.8 | length 1503.2
  Top Layer w12: RN23.4@3381.51,2832 3381.51,2853.51 3408,2880 3661,2880 ; RN23.4@3383.39,2843.81 cw(c3411.33,2843.81) 3391.57,2863.57 ; RN23.3@3413.01,2832 3413.01,2878.01 ; RN23.2@3444.5,2832 3444.5,2879.5 ; RN24.4@3540.23,2832 3540.23,2879.23 ; RN24.8@3634.71,2758.85 3634.71,2767.71 3661,2794 3661,2880 ; RN24.8@3634.71,2772.54 ccw(c3634.71,2784.17) 3642.94,2775.94 ; RN25.8@3793.43,2758.85 3793.43,2776.43 3816.5,2799.5 3816.5,2880 ; RN25.8@3795.3,2770.66 cw(c3813.75,2770.66) 3800.71,2783.71 ; 3897.66,2961.16 ccw(c3826.81,3032) J4.1@3927,3032 ; 3918.14,2981.64 ccw(c3867.78,3032) J4.1@3939,3032 ; 3930.25,2993.75 cw(c3955,2968.99) J4.1@3955,3004 ; J4.1@3938.63,3002.13 ccw(c3908.75,3032) J4.1@3951,3032 ; J4.1@3955,3032 3955,3018.5 3816.5,2880 ; 3661,2880 3739.5,2880 3816.5,2880
  Bottom Layer w20: J4.1@3938.03,3015.03 cw(c3897.06,2974.06) 3955,2974.06 cw(c4012.94,2974.06) J4.1@3971.97,3015.03 ; C38.1@3955,2941 J4.1@3955,3032
RESET: R21.1 U6.L3 | length 2288.6
  Top Layer w5: U6.L3@2656.43,1451.11 cw(c2656.43,1435.76) 2667.28,1446.61 cw(c2678.13,1457.46) U6.L3@2662.78,1457.46 ; U6.L3@2656.43,1457.46 v1(2676.11,1437.78) ; U6.L3@2658.78,1451.52 cw(c2648.7,1434.06) v1@2668.68,1436.77 ; U6.L3@2662.37,1455.11 ccw(c2679.83,1465.19) v1@2677.12,1445.21 ; 2665.66,1447.54 cw(c2662.21,1441.56) v1@2668.87,1439.75 ; 2666.35,1448.23 ccw(c2672.33,1451.68) v1@2674.14,1445.02 ; 2667.47,1446.28 ccw(c2678.1,1452.42) v1@2676.45,1440.26 ; 2667.61,1446.42 cw(c2661.47,1435.79) v1@2673.63,1437.44 ; v1@2668.61,1437.78 ccw(c2650.5,1437.78) 2663.31,1450.58 ccw(c2676.11,1463.39) v1@2676.11,1445.28 ; v1@2674.17,1445.02 cw(c2672.34,1451.85) 2668.81,1445.73 ccw(c2672.34,1451.85) v1@2674.17,1445.02 ; 2668.16,1445.08 cw(c2662.04,1441.55) 2668.87,1439.72 ccw(c2662.04,1441.55) 2668.16,1445.08
  Mid-Layer 1 w5: 2660.71,1418.71 ccw(c2641.65,1437.78) v1@2668.61,1437.78 ; 2669.25,1427.25 ccw(c2658.72,1437.78) v1@2673.61,1437.78 ; 2669.57,1427.57 cw(c2676.11,1421.03) v1@2676.11,1430.28 ; v1(2676.11,1437.78) 2676.11,1434.11 2658,1416 2658,1333 2792,1199 2995,1199 3865,329 v1(3981,329) ; v1@3975.7,323.7 ccw(c3962.89,310.89) 3962.89,329 ccw(c3962.89,347.11) v1@3975.7,334.3
  Bottom Layer w5: R21.1@3971.58,306.67 ccw(c3949.83,329) v1(3981,329) ; v1@3974.85,324.71 cw(c3963.68,316.94) 3976.82,313.41 cw(c3989.97,309.89) v1@3984.19,322.21 ; R21.1@3975.07,303.09 ccw(c3961.37,317.15) 3981,317.15 ccw(c4000.63,317.15) R21.1@3986.93,303.09 ; v1@3975.7,323.7 cw(c3962.89,310.89) 3981,310.89 cw(c3999.11,310.89) v1@3986.3,323.7 ; v1@3977.81,322.21 cw(c3972.03,309.89) 3985.18,313.41 cw(c3998.32,316.94) v1@3987.15,324.71 ; R21.1@3981,297 v1(3981,329) ; R21.1@3990.42,306.67 cw(c4012.17,329) v1(3981,329)
RTC_DATA: R25.2 U6.D14 U11.6 | length 870.4
  Top Layer w5: v1@2200,2141 v1(2201,2142) U11.6@2254,2142 ; v1@2206.3,2136.7 cw(c2219.11,2123.89) 2219.11,2142 cw(c2219.11,2160.11) v1@2206.3,2147.3 ; U11.6@2229.28,2135.28 ccw(c2213.07,2119.07) 2213.07,2142 ccw(c2213.07,2164.93) U11.6@2229.28,2148.72 ; v1@2360.14,1902.79 cw(c2357.43,1882.81) U6.D14@2374.89,1892.89 ; v1@2360.81,1907.74 cw(c2359.16,1895.58) 2369.79,1901.72 ; v1@2361.15,1902.72 cw(c2361.15,1884.61) 2373.95,1897.42 cw(c2386.76,1910.22) v1@2368.65,1910.22 ; v1(2361.15,1910.22) U6.D14@2380.83,1890.54 ; v1@2363.63,1910.56 ccw(c2375.79,1912.21) 2369.65,1901.58 ; v1@2368.39,1908.25 ccw(c2375.05,1906.44) 2371.6,1900.46 ; v1@2368.58,1911.23 ccw(c2388.56,1913.94) U6.D14@2378.48,1896.48 ; 2370.91,1899.77 ccw(c2364.93,1896.32) v1@2363.12,1902.98 ; U6.D14@2374.48,1890.54 ccw(c2359.13,1890.54) 2369.98,1901.39 ccw(c2380.83,1912.24) U6.D14@2380.83,1896.89 ; v1@2363.09,1902.98 cw(c2364.92,1896.15) 2368.45,1902.27 ccw(c2364.92,1896.15) v1@2363.09,1902.98 ; v1@2368.39,1908.28 ccw(c2375.22,1906.45) 2369.1,1902.92 cw(c2375.22,1906.45) v1@2368.39,1908.28
  Mid-Layer 1 w5: v1@2201,2134.5 cw(c2201,2116.39) 2213.8,2129.2 cw(c2226.61,2142) v1@2208.5,2142 ; v1(2201,2142) 2341.46,2001.54 2341.46,1941.54 ; 2349.57,1933.43 cw(c2327.61,1911.46) v1@2358.65,1910.31 ; v1@2353.65,1910.5 ccw(c2311.97,1912.04) 2341.47,1941.53 ; 2357.68,1925.32 cw(c2343.25,1910.88) v1@2363.65,1910.13 ; v1@2358.05,1917.05 ccw(c2355.88,1921.85) 2361.15,1921.85 ; v1(2361.15,1910.22) 2361.15,1921.85 ; v1@2364.24,1917.05 cw(c2366.41,1921.85) 2361.15,1921.85 ; 2341.46,1941.54 2361.15,1921.85
  Bottom Layer w6: v1(2201,2142) R25.2@2239,2142 ; v1@2204.5,2148.06 ccw(c2215.25,2166.68) 2220.81,2145.91 ; v1@2205.95,2137.05 cw(c2217.9,2125.1) 2217.9,2142 cw(c2217.9,2158.9) v1@2205.95,2146.95 ; v1@2206.2,2142 ccw(c2206.2,2176.8) R25.2@2230.81,2152.19 ; v1@2207.06,2138.5 cw(c2217.72,2132.35) 2214.53,2144.23 ; 2211.03,2142 cw(c2211.03,2114.03) R25.2@2230.81,2133.81 ; 2220.69,2142 ccw(c2220.69,2162.31) R25.2@2235.05,2147.95
RTC_NRST: R26.2 U6.C13 U11.5 | length 817.6
  Top Layer w5: v1(2201,2092) U11.5@2254,2092 ; v1@2206.3,2086.7 cw(c2219.11,2073.89) 2219.11,2092 cw(c2219.11,2110.11) v1@2206.3,2097.3 ; U11.5@2229.28,2085.28 ccw(c2213.07,2069.07) 2213.07,2092 ccw(c2213.07,2114.93) U11.5@2229.28,2098.72 ; v1@2320.77,1863.42 cw(c2318.06,1843.44) U6.C13@2335.52,1853.52 ; v1@2321.44,1868.37 cw(c2319.79,1856.21) 2330.42,1862.35 ; v1@2321.78,1863.35 cw(c2321.78,1845.24) 2334.58,1858.05 cw(c2347.39,1870.85) v1@2329.28,1870.85 ; v1(2321.78,1870.85) U6.C13@2341.46,1851.17 ; v1@2323.75,1863.61 cw(c2325.56,1856.95) 2331.54,1860.4 ; v1@2324.26,1871.19 ccw(c2336.42,1872.84) 2330.28,1862.21 ; v1@2329.21,1871.86 ccw(c2349.19,1874.57) U6.C13@2339.11,1857.11 ; 2332.23,1861.09 cw(c2335.68,1867.07) v1@2329.02,1868.88 ; U6.C13@2335.11,1851.17 ccw(c2319.76,1851.17) 2330.61,1862.02 ccw(c2341.46,1872.87) U6.C13@2341.46,1857.52 ; v1@2329.02,1868.91 ccw(c2335.85,1867.08) 2329.73,1863.55 cw(c2335.85,1867.08) v1@2329.02,1868.91 ; v1@2323.72,1863.61 cw(c2325.55,1856.78) 2329.08,1862.9 ccw(c2325.55,1856.78) v1@2323.72,1863.61
  Mid-Layer 1 w5: v1@2195.7,2086.7 cw(c2182.89,2073.89) 2201,2073.89 cw(c2219.11,2073.89) v1@2206.3,2086.7 ; v1(2201,2092) 2201,2061 2341,1921 2341,1890.07 v1(2321.78,1870.85) ; v1@2321.78,1878.35 ccw(c2321.78,1896.46) 2334.58,1883.65 ccw(c2347.39,1870.85) v1@2329.28,1870.85
  Bottom Layer w6: v1@2204.51,2085.94 cw(c2212.94,2071.41) 2217.28,2087.64 cw(c2221.63,2103.86) v1@2207.07,2095.49 ; v1@2205.95,2087.05 cw(c2217.9,2075.1) 2217.9,2092 cw(c2217.9,2108.9) v1@2205.95,2096.95 ; 2211.64,2092 cw(c2211.64,2065.86) R26.2@2234.01,2079.38 ; 2222.27,2092 cw(c2222.27,2072.29) R26.2@2239.14,2082.48 ; R26.2@2228.87,2076.28 ccw(c2201,2059.43) v1(2201,2092) 2231,2092 R26.2@2240,2083
RTC_SCLK: R27.2 U6.E13 U11.7 | length 935.9
  Top Layer w5: v1(2202,2192) U11.7@2254,2192 ; v1@2207.3,2186.7 cw(c2220.11,2173.89) 2220.11,2192 cw(c2220.11,2210.11) v1@2207.3,2197.3 ; U11.7@2229.28,2185.28 ccw(c2213.07,2169.07) 2213.07,2192 ccw(c2213.07,2214.93) U11.7@2229.28,2198.72 ; v1@2399.51,1863.42 cw(c2396.8,1843.44) U6.E13@2414.26,1853.52 ; v1@2400.18,1868.37 cw(c2398.53,1856.21) 2409.16,1862.35 ; v1@2400.52,1863.35 cw(c2400.52,1845.24) 2413.32,1858.05 cw(c2426.13,1870.85) v1@2408.02,1870.85 ; v1(2400.52,1870.85) U6.E13@2420.2,1851.17 ; v1@2402.49,1863.61 cw(c2404.3,1856.95) 2410.28,1860.4 ; v1@2403,1871.19 ccw(c2415.16,1872.84) 2409.02,1862.21 ; v1@2407.95,1871.86 ccw(c2427.93,1874.57) U6.E13@2417.85,1857.11 ; 2410.97,1861.09 cw(c2414.42,1867.07) v1@2407.76,1868.88 ; U6.E13@2413.85,1851.17 ccw(c2398.5,1851.17) 2409.35,1862.02 ccw(c2420.2,1872.87) U6.E13@2420.2,1857.52 ; v1@2407.76,1868.91 ccw(c2414.59,1867.08) 2408.47,1863.55 cw(c2414.59,1867.08) v1@2407.76,1868.91 ; v1@2402.46,1863.61 cw(c2404.29,1856.78) 2407.82,1862.9 ccw(c2404.29,1856.78) v1@2402.46,1863.61
  Mid-Layer 1 w5: v1@2202,2184.5 cw(c2202,2166.39) 2214.8,2179.2 cw(c2227.61,2192) v1@2209.5,2192 ; v1(2202,2192) 2381,2013 2381,1890.37 v1(2400.52,1870.85) ; v1@2393.02,1870.85 ccw(c2374.91,1870.85) 2387.72,1883.65 ccw(c2400.52,1896.46) v1@2400.52,1878.35
  Bottom Layer w6: v1@2206,2197.74 ccw(c2213.26,2208.15) 2216.54,2195.9 ccw(c2219.83,2183.64) v1@2208.34,2189.03 ; v1@2206.63,2197.25 ccw(c2216,2207.87) 2219.67,2194.19 ; v1@2206.95,2187.05 cw(c2218.9,2175.1) 2218.9,2192 cw(c2218.9,2208.9) v1@2206.95,2196.95 ; v1@2208.06,2188.5 cw(c2215.43,2184.25) 2213.23,2192.46 ; v1@2211.5,2192 ccw(c2211.5,2216.56) R27.2@2233.68,2206.01 ; 2221,2192 ccw(c2221,2212.04) R27.2@2239.1,2203.43 ; R27.2@2228.26,2208.59 cw(c2202,2221.08) v1(2202,2192) R27.2@2229,2192
RXD: R7.1 U4.26 U6.C11 | length 2376.9
  Top Layer w5: U4.26@789.21,2725.42 935.58,2725.42 v1(956,2705) R7.1@991,2705 ; U4.26@809.51,2723.43 cw(c814.32,2718.62) 814.32,2725.42 cw(c814.32,2732.21) U4.26@809.51,2727.41 ; v1@948.5,2705 ccw(c930.39,2705) 943.2,2717.8 ccw(c956,2730.61) v1@956,2712.5 ; v1@960.12,2698.73 cw(c969.32,2684.72) 973.66,2700.91 ; v1@960.12,2711.27 ccw(c969.32,2725.28) 973.66,2709.09 ; v1@961.3,2699.7 cw(c974.11,2686.89) 974.11,2705 cw(c974.11,2723.11) v1@961.3,2710.3 ; v1@962.5,2701.25 cw(c976.33,2693.26) 972.2,2708.69 ; v1@962.5,2708.75 ccw(c976.33,2716.74) 972.2,2701.31 ; R7.1@981.45,2695.45 ccw(c958.41,2672.41) 958.41,2705 ccw(c958.41,2737.59) R7.1@981.45,2714.55 ; R7.1@984.99,2698.99 ccw(c970.48,2684.48) 970.48,2705 ccw(c970.48,2725.52) R7.1@984.99,2711.01 ; v1@2320.77,1784.68 cw(c2318.06,1764.7) U6.C11@2335.52,1774.78 ; v1@2321.44,1789.63 cw(c2319.79,1777.47) 2330.42,1783.61 ; v1@2321.78,1784.61 cw(c2321.78,1766.5) 2334.58,1779.31 cw(c2347.39,1792.11) v1@2329.28,1792.11 ; v1(2321.78,1792.11) U6.C11@2341.46,1772.43 ; v1@2323.75,1784.87 cw(c2325.56,1778.21) 2331.54,1781.66 ; v1@2324.26,1792.45 ccw(c2336.42,1794.1) 2330.28,1783.47 ; v1@2329.21,1793.12 ccw(c2349.19,1795.83) U6.C11@2339.11,1778.37 ; 2332.23,1782.35 cw(c2335.68,1788.33) v1@2329.02,1790.14 ; U6.C11@2335.11,1772.43 ccw(c2319.76,1772.43) 2330.61,1783.28 ccw(c2341.46,1794.13) U6.C11@2341.46,1778.78 ; v1@2329.02,1790.17 ccw(c2335.85,1788.34) 2329.73,1784.81 cw(c2335.85,1788.34) v1@2329.02,1790.17 ; v1@2323.72,1784.87 cw(c2325.55,1778.04) 2329.08,1784.16 ccw(c2325.55,1778.04) v1@2323.72,1784.87
  Mid-Layer 1 w5: v1@956,2697.5 cw(c956,2679.39) 968.8,2692.2 cw(c981.61,2705) v1@963.5,2705 ; v1(956,2705) 1847,1814 2289,1814 2310.89,1792.11 ; v1@2314.77,1789.44 ccw(c2310.89,1787.96) 2310.89,1792.11 ; v1@2314.77,1794.79 cw(c2310.89,1796.27) 2310.89,1792.11 ; v1(2321.78,1792.11) 2310.89,1792.11
S_A0: U6.J3 U9.23 | length 1798.3
  Top Layer w5: U6.J3@2577.68,1451.11 cw(c2577.68,1435.76) 2588.54,1446.61 cw(c2599.39,1457.46) U6.J3@2584.04,1457.46 ; U6.J3@2577.68,1457.46 v1(2597.37,1437.78) ; U6.J3@2580.04,1451.52 cw(c2569.96,1434.06) v1@2589.94,1436.77 ; U6.J3@2583.63,1455.11 ccw(c2601.09,1465.19) v1@2598.38,1445.21 ; 2586.92,1447.54 cw(c2583.47,1441.56) v1@2590.13,1439.75 ; 2587.61,1448.23 ccw(c2593.59,1451.68) v1@2595.4,1445.02 ; 2588.73,1446.28 ccw(c2599.36,1452.42) v1@2597.71,1440.26 ; 2588.87,1446.42 cw(c2582.73,1435.79) v1@2594.89,1437.44 ; v1@2589.87,1437.78 ccw(c2571.76,1437.78) 2584.57,1450.58 ccw(c2597.37,1463.39) v1@2597.37,1445.28 ; v1@3232.61,487.61 cw(c3219.81,474.81) 3237.91,474.81 cw(c3256.02,474.81) v1@3243.22,487.61 ; U9.23@3233.67,470.24 ccw(c3223.43,480.49) 3237.91,480.49 ccw(c3252.4,480.49) U9.23@3242.16,470.24 ; U9.23@3237.91,437 v1(3237.91,492.91) ; 2589.42,1445.08 cw(c2583.3,1441.55) 2590.13,1439.72 ccw(c2583.3,1441.55) 2589.42,1445.08 ; 2590.07,1445.73 ccw(c2593.6,1451.85) 2595.43,1445.02 cw(c2593.6,1451.85) 2590.07,1445.73
  Mid-Layer 1 w5: v1@2594.01,1431.07 cw(c2591.28,1425.63) 2597.37,1425.63 ; v1@2594.89,1438.05 ccw(c2613.54,1436) 2600.27,1422.73 ; v1(2597.37,1437.78) 2597.37,1425.63 ; v1@2599.86,1437.5 ccw(c2626.8,1434.54) 2607.63,1415.37 ; v1@2600.73,1431.07 ccw(c2603.46,1425.63) 2597.37,1425.63 ; v1@2604.83,1436.96 ccw(c2640.07,1433.08) 2615,1408 ; v1@3232.61,498.22 ccw(c3219.81,511.02) 3237.91,511.02 ccw(c3256.02,511.02) v1@3243.22,498.22 ; v1(3237.91,492.91) 3237.91,666 ccw(c3232.91,666) 3232.91,671 3222.21,671 cw(c3222.21,676) 3217.21,676 cw(c3222.21,676) 3222.21,681 3253.62,681 ccw(c3253.62,686) 3258.62,686 ccw(c3253.62,686) 3253.62,691 3222.21,691 cw(c3222.21,696) 3217.21,696 cw(c3222.21,696) 3222.21,701 3253.62,701 ccw(c3253.62,706) 3258.62,706 ccw(c3253.62,706) 3253.62,711 3242.91,711 cw(c3242.91,716) 3237.91,716 3237.91,749.09 2921,1066 2849,1066 2615,1300 2615,1408 ; 2597.37,1425.63 2615,1408
S_A1: U6.J4 U9.24 | length 1744.6
  Top Layer w5: U6.J4@2577.68,1490.48 cw(c2577.68,1475.13) 2588.54,1485.98 cw(c2599.39,1496.83) U6.J4@2584.04,1496.83 ; U6.J4@2577.68,1496.83 v1(2597.37,1477.15) ; U6.J4@2580.04,1490.89 cw(c2569.96,1473.43) v1@2589.94,1476.14 ; U6.J4@2583.63,1494.48 ccw(c2601.09,1504.56) v1@2598.38,1484.58 ; 2586.92,1486.91 cw(c2583.47,1480.93) v1@2590.13,1479.12 ; 2587.61,1487.6 ccw(c2593.59,1491.05) v1@2595.4,1484.39 ; 2588.73,1485.65 ccw(c2599.36,1491.79) v1@2597.71,1479.63 ; 2588.87,1485.79 cw(c2582.73,1475.16) v1@2594.89,1476.81 ; v1@2589.87,1477.15 ccw(c2571.76,1477.15) 2584.57,1489.95 ccw(c2597.37,1502.76) v1@2597.37,1484.65 ; v1@3264.11,486.29 cw(c3251.3,473.48) 3269.41,473.48 cw(c3287.52,473.48) v1@3274.71,486.29 ; U9.24@3265.17,470.24 ccw(c3254.92,480.49) 3269.41,480.49 ccw(c3283.89,480.49) U9.24@3273.65,470.24 ; U9.24@3269.41,437 v1(3269.41,491.59) ; v1@2590.13,1479.09 ccw(c2583.3,1480.92) 2589.42,1484.45 cw(c2583.3,1480.92) v1@2590.13,1479.09 ; 2590.07,1485.1 ccw(c2593.6,1491.22) 2595.43,1484.39 cw(c2593.6,1491.22) 2590.07,1485.1
  Mid-Layer 1 w5: v1@2597.37,1469.65 cw(c2597.37,1451.54) 2610.17,1464.35 cw(c2622.98,1477.15) v1@2604.87,1477.15 ; v1(2597.37,1477.15) 2617,1457.52 2617,1425 2625,1417 2625,1308 2851,1082 2931,1082 3269.41,743.59 3269.41,656 ccw(c3274.41,656) 3274.41,651 3282.47,651 cw(c3282.47,646) 3287.47,646 cw(c3282.47,646) 3282.47,641 3256.35,641 ccw(c3256.35,636) 3251.35,636 ccw(c3256.35,636) 3256.35,631 3282.47,631 cw(c3282.47,626) 3287.47,626 cw(c3282.47,626) 3282.47,621 3274.41,621 ccw(c3274.41,616) 3269.41,616 v1(3269.41,491.59) ; v1@3264.11,496.89 ccw(c3251.3,509.7) 3269.41,509.7 ccw(c3287.52,509.7) v1@3274.71,496.89
S_A2: U6.K3 U9.25 | length 1746.9
  Top Layer w5: U6.K3@2617.06,1451.11 cw(c2617.06,1435.76) 2627.91,1446.61 cw(c2638.76,1457.46) U6.K3@2623.41,1457.46 ; U6.K3@2617.06,1457.46 v1(2636.74,1437.78) ; U6.K3@2619.41,1451.52 cw(c2609.33,1434.06) v1@2629.31,1436.77 ; U6.K3@2623,1455.11 ccw(c2640.46,1465.19) v1@2637.75,1445.21 ; 2626.29,1447.54 cw(c2622.84,1441.56) v1@2629.5,1439.75 ; 2626.98,1448.23 ccw(c2632.96,1451.68) v1@2634.77,1445.02 ; 2628.1,1446.28 ccw(c2638.73,1452.42) v1@2637.08,1440.26 ; 2628.24,1446.42 cw(c2622.1,1435.79) v1@2634.26,1437.44 ; v1@2629.24,1437.78 ccw(c2611.13,1437.78) 2623.94,1450.58 ccw(c2636.74,1463.39) v1@2636.74,1445.28 ; v1@3295.6,485.6 cw(c3282.8,472.8) 3300.91,472.8 cw(c3319.01,472.8) v1@3306.21,485.6 ; U9.25@3296.66,470.24 ccw(c3286.42,480.49) 3300.91,480.49 ccw(c3315.39,480.49) U9.25@3305.15,470.24 ; U9.25@3300.91,437 v1(3300.91,490.91) ; 2628.79,1445.08 cw(c2622.67,1441.55) 2629.5,1439.72 ccw(c2622.67,1441.55) 2628.79,1445.08 ; 2629.44,1445.73 ccw(c2632.97,1451.85) 2634.8,1445.02 cw(c2632.97,1451.85) 2629.44,1445.73
  Mid-Layer 1 w5: v1@2631.44,1432.48 cw(c2618.63,1419.67) 2636.74,1419.67 cw(c2654.85,1419.67) v1@2642.04,1432.48 ; v1(2636.74,1437.78) 2636.74,1316.26 2858,1095 2943,1095 3300.91,737.09 3300.91,599 ccw(c3305.91,599) 3305.91,594 3315.24,594 cw(c3315.24,589) 3320.24,589 cw(c3315.24,589) 3315.24,584 3286.57,584 ccw(c3286.57,579) 3281.57,579 ccw(c3286.57,579) 3286.57,574 3315.24,574 cw(c3315.24,569) 3320.24,569 cw(c3315.24,569) 3315.24,564 3286.57,564 ccw(c3286.57,559) 3281.57,559 ccw(c3286.57,559) 3286.57,554 3295.91,554 cw(c3295.91,549) 3300.91,549 v1(3300.91,490.91) ; v1@3295.6,496.21 ccw(c3282.8,509.01) 3300.91,509.01 ccw(c3319.01,509.01) v1@3306.21,496.21
S_A3: U6.K5 U9.26 | length 1784.7
  Top Layer w5: U6.K5@2617.06,1529.85 cw(c2617.06,1514.5) 2627.91,1525.35 cw(c2638.76,1536.2) U6.K5@2623.41,1536.2 ; U6.K5@2617.06,1536.2 v1(2636.74,1516.52) ; U6.K5@2619.41,1530.26 cw(c2609.33,1512.8) v1@2629.31,1515.51 ; U6.K5@2623,1533.85 ccw(c2640.46,1543.93) v1@2637.75,1523.95 ; 2626.29,1526.28 cw(c2622.84,1520.3) v1@2629.5,1518.49 ; 2626.98,1526.97 ccw(c2632.96,1530.42) v1@2634.77,1523.76 ; 2628.1,1525.02 ccw(c2638.73,1531.16) v1@2637.08,1519 ; 2628.24,1525.16 cw(c2622.1,1514.53) v1@2634.26,1516.18 ; v1@2629.24,1516.52 ccw(c2611.13,1516.52) 2623.94,1529.32 ccw(c2636.74,1542.13) v1@2636.74,1524.02 ; v1@3327.1,485.1 cw(c3314.3,472.29) 3332.4,472.29 cw(c3350.51,472.29) v1@3337.7,485.1 ; U9.26@3328.16,470.24 ccw(c3317.92,480.49) 3332.4,480.49 ccw(c3346.89,480.49) U9.26@3336.64,470.24 ; v1@3328.65,483.91 cw(c3323.98,475.81) 3333.01,478.23 ; v1@3328.89,483.77 cw(c3326.34,478.95) 3331.61,477.54 ; 3331.8,478.23 cw(c3340.82,475.81) v1@3336.15,483.91 ; U9.26@3332.4,437 v1(3332.4,490.4) ; 3333.19,477.54 cw(c3338.46,478.95) v1@3335.91,483.77 ; 2628.79,1523.82 cw(c2622.67,1520.29) 2629.5,1518.46 ccw(c2622.67,1520.29) 2628.79,1523.82 ; 2629.44,1524.47 ccw(c2632.97,1530.59) 2634.8,1523.76 cw(c2632.97,1530.59) 2629.44,1524.47
  Mid-Layer 1 w5: v1@2636.74,1509.02 cw(c2636.74,1490.91) 2649.54,1503.72 cw(c2662.35,1516.52) v1@2644.24,1516.52 ; v1(2636.74,1516.52) 2656,1497.26 2656,1431 2648,1423 2648,1324 2864,1108 2957,1108 3332.4,732.6 3332.4,706 ccw(c3337.4,706) 3337.4,701 3350.96,701 cw(c3350.96,696) 3355.96,696 cw(c3350.96,696) 3350.96,691 3337.4,691 ccw(c3337.4,686) 3332.4,686 v1(3332.4,490.4) ; v1@3327.1,495.7 ccw(c3314.3,508.51) 3332.4,508.51 ccw(c3350.51,508.51) v1@3337.7,495.7
S_A4: U6.P1 U9.29 | length 1578.9
  Top Layer w5: U6.P1@2770.89,1378.72 ccw(c2789.29,1378.72) 2776.28,1365.72 ; U6.P1@2771.25,1373.28 cw(c2767.75,1367.47) 2774.54,1367.47 ; U6.P1@2774.54,1378.72 2774.54,1367.46 ; U6.P1@2775.89,1378.72 ccw(c2806.36,1378.72) 2784.82,1357.18 ; U6.P1@2777.82,1373.28 ccw(c2781.33,1367.47) 2774.54,1367.47 ; U6.P1@2780.89,1378.72 ccw(c2823.43,1378.72) 2793.35,1348.65 ; U9.29@3328.16,930.24 ccw(c3317.92,940.49) 3332.4,940.49 ccw(c3346.89,940.49) U9.29@3336.64,930.24 ; U9.29@3332.4,897 3332.4,975.6 3095.5,1212.5 cw(c3099.03,1216.04) 3095.5,1219.57 3102.39,1226.47 ccw(c3098.86,1230) 3102.39,1233.54 ccw(c3098.86,1230) 3095.32,1233.54 3074.46,1212.68 cw(c3070.93,1216.22) 3067.39,1212.68 cw(c3070.93,1216.22) 3067.39,1219.75 3088.25,1240.61 ccw(c3084.71,1244.14) 3088.25,1247.68 ccw(c3084.71,1244.14) 3081.18,1247.68 3060.32,1226.82 cw(c3056.78,1230.36) 3053.25,1226.82 cw(c3056.78,1230.36) 3053.25,1233.89 3074.11,1254.75 ccw(c3070.57,1258.29) 3074.11,1261.82 ccw(c3070.57,1258.29) 3067.04,1261.82 3060.14,1254.93 cw(c3056.61,1258.46) 3053.07,1254.93 3046,1262 3039,1262 ccw(c3039,1257) 3034,1257 3034,1247.25 cw(c3029,1247.25) 3029,1242.25 cw(c3029,1247.25) 3024,1247.25 3024,1276.75 ccw(c3019,1276.75) 3019,1281.75 ccw(c3019,1276.75) 3014,1276.75 3014,1247.25 cw(c3009,1247.25) 3009,1242.25 cw(c3009,1247.25) 3004,1247.25 3004,1276.75 ccw(c2999,1276.75) 2999,1281.75 ccw(c2999,1276.75) 2994,1276.75 2994,1247.25 cw(c2989,1247.25) 2989,1242.25 cw(c2989,1247.25) 2984,1247.25 2984,1276.75 ccw(c2979,1276.75) 2979,1281.75 ccw(c2979,1276.75) 2974,1276.75 2974,1247.25 cw(c2969,1247.25) 2969,1242.25 cw(c2969,1247.25) 2964,1247.25 2964,1276.75 ccw(c2959,1276.75) 2959,1281.75 ccw(c2959,1276.75) 2954,1276.75 2954,1247.25 cw(c2949,1247.25) 2949,1242.25 cw(c2949,1247.25) 2944,1247.25 2944,1276.75 ccw(c2939,1276.75) 2939,1281.75 ccw(c2939,1276.75) 2934,1276.75 2934,1247.25 cw(c2929,1247.25) 2929,1242.25 cw(c2929,1247.25) 2924,1247.25 2924,1276.75 ccw(c2919,1276.75) 2919,1281.75 ccw(c2919,1276.75) 2914,1276.75 2914,1247.25 cw(c2909,1247.25) 2909,1242.25 cw(c2909,1247.25) 2904,1247.25 2904,1276.75 ccw(c2899,1276.75) 2899,1281.75 ccw(c2899,1276.75) 2894,1276.75 2894,1267 cw(c2889,1267) 2889,1262 2880,1262 2774.54,1367.46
